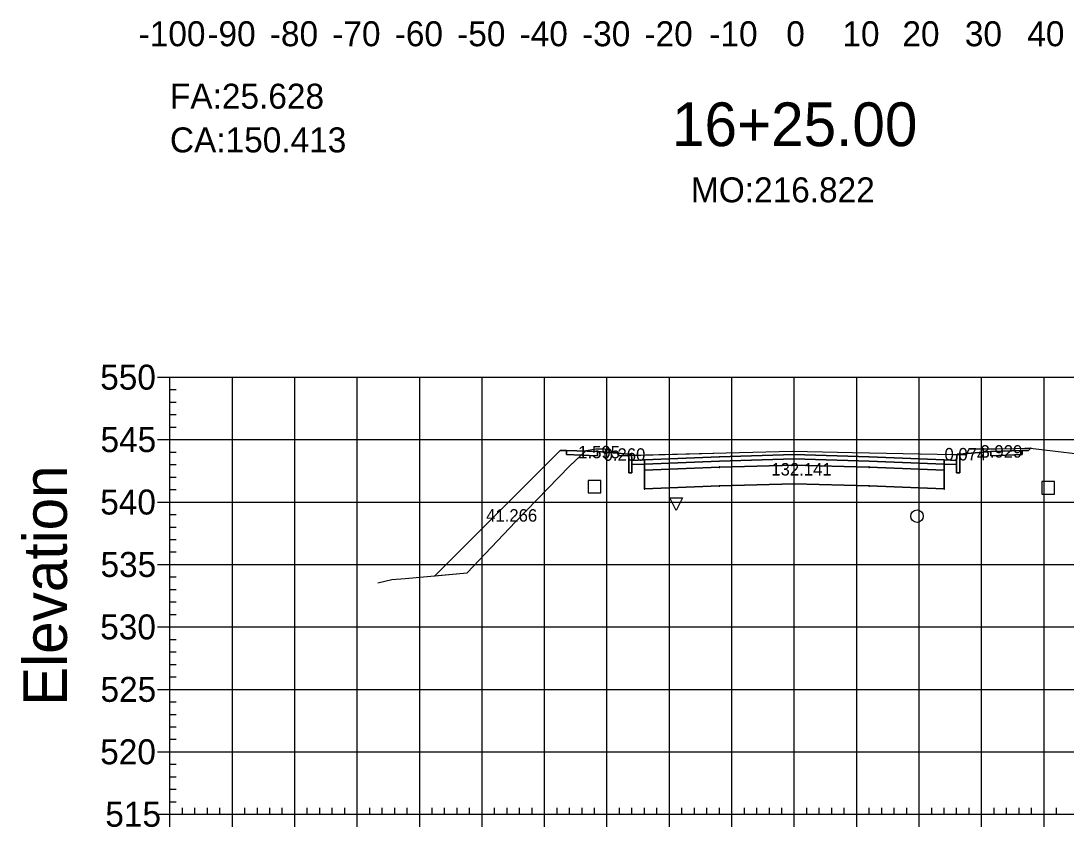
# Model space of a CAD drawing. Extents: x 704834 to 709892, y 372981 to 377533.
# Drawn here: x 704913 to 705080.4, y 373420.8 to 373549.9 of the extents above; entities that cross this region are included whole.
import ezdxf

# ---------------------------------------------------------------- set-up
doc = ezdxf.new("R2010")
doc.units = 0
for name, color, linetype in [('1', 7, 'Continuous'), ('10', 7, 'Continuous'), ('13', 7, 'Continuous'), ('14', 7, 'Continuous'), ('4', 7, 'Continuous'), ('57', 7, 'Continuous'), ('59', 7, 'Continuous'), ('60', 7, 'Continuous'), ('Default_Xsect', 7, 'Continuous'), ('Existing', 7, 'Continuous')]:
    doc.layers.add(name, color=color, linetype=linetype)

msp = doc.modelspace()

# ---------------------------------------------------------------- linework, layer by layer
for points in [[(704999.37, 373481.06), (704979.32, 373461)], [(705000.37, 373481.1), (704999.37, 373481.06)], [(705010.37, 373480.5), (705005.37, 373480.9)], [(705063.37, 373480.5), (705068.37, 373480.9)], [(705073.37, 373481.1), (705074.37, 373481.06)], [(705074.37, 373481.06), (705074.75, 373481.43)]]:
    msp.add_lwpolyline(points)
for points in [[(705005.37, 373480.9), (705000.37, 373481.1), (705000.37, 373480.43), (705005.37, 373480.23)], [(705068.37, 373480.23), (705073.37, 373480.43), (705073.37, 373481.1), (705068.37, 373480.9)], [(705010.87, 373479.5), (705010.79, 373480.5), (705010.37, 373480.5), (705010.37, 373477.5), (705010.87, 373477.5)], [(705012.87, 373479.58), (705010.87, 373479.5), (705010.87, 373478.83), (705012.87, 373478.91)], [(705036.87, 373479.75), (705048.87, 373479.39), (705060.87, 373478.91), (705060.87, 373479.58), (705048.87, 373480.06), (705036.87, 373480.42), (705024.87, 373480.06), (705012.87, 373479.58), (705012.87, 373478.91), (705024.87, 373479.39)], [(705036.87, 373478.75), (705048.87, 373478.39), (705060.87, 373477.91), (705060.87, 373478.91), (705048.87, 373479.39), (705036.87, 373479.75), (705024.87, 373479.39), (705012.87, 373478.91), (705012.87, 373477.91), (705024.87, 373478.39)], [(705036.82, 373479.7), (705036.92, 373479.7), (705036.92, 373479.8), (705036.82, 373479.8)], [(705060.87, 373478.91), (705062.87, 373478.83), (705062.87, 373479.5), (705060.87, 373479.58)], [(705062.87, 373477.5), (705063.37, 373477.5), (705063.37, 373480.5), (705062.96, 373480.5), (705062.87, 373479.5)], [(705012.82, 373477.86), (705012.92, 373477.86), (705012.92, 373477.96), (705012.82, 373477.96)], [(705036.87, 373475.75), (705048.87, 373475.39), (705060.87, 373474.91), (705060.87, 373477.91), (705048.87, 373478.39), (705036.87, 373478.75), (705024.87, 373478.39), (705012.87, 373477.91), (705012.87, 373474.91), (705024.87, 373475.39)], [(705024.82, 373478.34), (705024.92, 373478.34), (705024.92, 373478.44), (705024.82, 373478.44)], [(705036.82, 373478.7), (705036.92, 373478.7), (705036.92, 373478.8), (705036.82, 373478.8)], [(705048.82, 373478.34), (705048.92, 373478.34), (705048.92, 373478.44), (705048.82, 373478.44)], [(705060.82, 373477.86), (705060.92, 373477.86), (705060.92, 373477.96), (705060.82, 373477.96)], [(705012.82, 373474.86), (705012.92, 373474.86), (705012.92, 373474.96), (705012.82, 373474.96)], [(705024.82, 373475.34), (705024.92, 373475.34), (705024.92, 373475.44), (705024.82, 373475.44)], [(705036.82, 373475.7), (705036.92, 373475.7), (705036.92, 373475.8), (705036.82, 373475.8)], [(705048.82, 373475.34), (705048.92, 373475.34), (705048.92, 373475.44), (705048.82, 373475.44)], [(705060.82, 373474.86), (705060.92, 373474.86), (705060.92, 373474.96), (705060.82, 373474.96)]]:
    msp.add_lwpolyline(points, close=True)
at = {"layer": '1'}
for points in [[(704979.32, 373461), (704984.46, 373461.49), (704992.22, 373469.67), (705000.89, 373478.56), (705002.74, 373480.34), (705000.37, 373480.43), (705000.37, 373481.1), (704999.37, 373481.06)], [(705002.74, 373480.34), (705003.51, 373481.08), (705005.1, 373481.32), (705006.54, 373481.34), (705008.49, 373480.71), (705008.52, 373480.65), (705005.37, 373480.9), (705005.37, 373480.23)], [(705010.37, 373480.3), (705025.93, 373480.69), (705036.58, 373480.96), (705046.2, 373480.74), (705059.73, 373480.49), (705063.37, 373480.42), (705063.37, 373477.5), (705062.87, 373477.5), (705062.87, 373478.83), (705060.87, 373478.91), (705060.87, 373477.91), (705060.87, 373474.91), (705048.87, 373475.39), (705036.87, 373475.75), (705024.87, 373475.39), (705012.87, 373474.91), (705012.87, 373477.91), (705012.87, 373478.91), (705010.87, 373478.83), (705010.87, 373477.5), (705010.37, 373477.5)], [(705064.54, 373480.59), (705064.82, 373481.24), (705064.88, 373481.34), (705065.07, 373481.34), (705069.08, 373481.35), (705069.21, 373481.36), (705072.04, 373481.4), (705073.81, 373481.43), (705074.14, 373481.44), (705074.66, 373481.44), (705074.75, 373481.43), (705074.37, 373481.06), (705073.37, 373481.1), (705073.37, 373480.43), (705068.37, 373480.23), (705068.37, 373480.9)], [(705008.52, 373480.65), (705008.71, 373480.25), (705010.37, 373480.3), (705010.37, 373480.5)], [(705063.37, 373480.42), (705064.45, 373480.4), (705064.54, 373480.59), (705063.37, 373480.5)], [(705017.94, 373471.49), (705016.94, 373473.49), (705018.94, 373473.49)]]:
    msp.add_lwpolyline(points, close=True, dxfattribs=at)
at = {"layer": '10'}
msp.add_lwpolyline([(705003.88, 373474.28), (705005.88, 373474.28), (705005.88, 373476.28), (705003.88, 373476.28)], close=True, dxfattribs=at)
at = {"layer": '13'}
msp.add_circle((705056.52, 373470.55), 1, dxfattribs=at)
at = {"layer": '14'}
for points in [[(705074.75, 373481.43), (705074.75, 373481.48), (705074.75, 373481.43), (705074.7, 373481.43), (705074.75, 373481.43), (705074.75, 373481.38), (705074.75, 373481.43), (705074.8, 373481.43)], [(705012.87, 373479.58), (705012.87, 373479.63), (705012.87, 373479.58), (705012.82, 373479.58), (705012.87, 373479.58), (705012.87, 373479.53), (705012.87, 373479.58), (705012.92, 373479.58)], [(705024.87, 373480.06), (705024.87, 373480.11), (705024.87, 373480.06), (705024.82, 373480.06), (705024.87, 373480.06), (705024.87, 373480.01), (705024.87, 373480.06), (705024.92, 373480.06)], [(705036.87, 373480.42), (705036.87, 373480.47), (705036.87, 373480.42), (705036.82, 373480.42), (705036.87, 373480.42), (705036.87, 373480.37), (705036.87, 373480.42), (705036.92, 373480.42)], [(705048.87, 373480.06), (705048.87, 373480.11), (705048.87, 373480.06), (705048.82, 373480.06), (705048.87, 373480.06), (705048.87, 373480.01), (705048.87, 373480.06), (705048.92, 373480.06)], [(705060.87, 373479.58), (705060.87, 373479.63), (705060.87, 373479.58), (705060.82, 373479.58), (705060.87, 373479.58), (705060.87, 373479.53), (705060.87, 373479.58), (705060.92, 373479.58)], [(704979.32, 373461), (704979.32, 373461.05), (704979.32, 373461), (704979.27, 373461), (704979.32, 373461), (704979.32, 373460.95), (704979.32, 373461), (704979.37, 373461)]]:
    msp.add_lwpolyline(points, dxfattribs=at)
at = {"layer": '4'}
msp.add_lwpolyline([(705076.52, 373474.1), (705078.52, 373474.1), (705078.52, 373476.1), (705076.52, 373476.1)], close=True, dxfattribs=at)
at = {"layer": '57'}
for p, q in [((704934.87, 373492.82), (704936.87, 373492.82)), ((704936.87, 373492.82), (705136.87, 373492.82)), ((704936.87, 373422.82), (704936.87, 373492.82)), ((704936.87, 373422.82), (704936.87, 373492.82)), ((704946.87, 373422.82), (704946.87, 373492.82)), ((704956.87, 373422.82), (704956.87, 373492.82)), ((704966.87, 373422.82), (704966.87, 373492.82)), ((704976.87, 373422.82), (704976.87, 373492.82)), ((704986.87, 373422.82), (704986.87, 373492.82)), ((704996.87, 373422.82), (704996.87, 373492.82)), ((705006.87, 373422.82), (705006.87, 373492.82)), ((705016.87, 373422.82), (705016.87, 373492.82)), ((705026.87, 373422.82), (705026.87, 373492.82)), ((705036.87, 373422.82), (705036.87, 373492.82)), ((705046.87, 373422.82), (705046.87, 373492.82)), ((705056.87, 373422.82), (705056.87, 373492.82)), ((705066.87, 373422.82), (705066.87, 373492.82)), ((705076.87, 373422.82), (705076.87, 373492.82)), ((704936.87, 373490.82), (704937.87, 373490.82)), ((704936.87, 373488.82), (704937.87, 373488.82)), ((704936.87, 373486.82), (704937.87, 373486.82)), ((704936.87, 373484.82), (704937.87, 373484.82)), ((704934.87, 373482.82), (704936.87, 373482.82)), ((704936.87, 373482.82), (705136.87, 373482.82)), ((704936.87, 373480.82), (704937.87, 373480.82)), ((704936.87, 373478.82), (704937.87, 373478.82)), ((704936.87, 373476.82), (704937.87, 373476.82)), ((704936.87, 373474.82), (704937.87, 373474.82)), ((704934.87, 373472.82), (704936.87, 373472.82)), ((704936.87, 373472.82), (705136.87, 373472.82)), ((704936.87, 373470.82), (704937.87, 373470.82)), ((704936.87, 373468.82), (704937.87, 373468.82)), ((704936.87, 373466.82), (704937.87, 373466.82)), ((704936.87, 373464.82), (704937.87, 373464.82)), ((704934.87, 373462.82), (704936.87, 373462.82)), ((704936.87, 373462.82), (705136.87, 373462.82)), ((704936.87, 373460.82), (704937.87, 373460.82)), ((704936.87, 373458.82), (704937.87, 373458.82)), ((704936.87, 373456.82), (704937.87, 373456.82)), ((704936.87, 373454.82), (704937.87, 373454.82)), ((704934.87, 373452.82), (704936.87, 373452.82)), ((704936.87, 373452.82), (705136.87, 373452.82)), ((704936.87, 373450.82), (704937.87, 373450.82)), ((704936.87, 373448.82), (704937.87, 373448.82)), ((704936.87, 373446.82), (704937.87, 373446.82)), ((704936.87, 373444.82), (704937.87, 373444.82)), ((704934.87, 373442.82), (704936.87, 373442.82)), ((704936.87, 373442.82), (705136.87, 373442.82)), ((704936.87, 373440.82), (704937.87, 373440.82)), ((704936.87, 373438.82), (704937.87, 373438.82)), ((704936.87, 373436.82), (704937.87, 373436.82)), ((704936.87, 373434.82), (704937.87, 373434.82)), ((704934.87, 373432.82), (704936.87, 373432.82)), ((704936.87, 373432.82), (705136.87, 373432.82)), ((704936.87, 373430.82), (704937.87, 373430.82)), ((704936.87, 373428.82), (704937.87, 373428.82)), ((704936.87, 373426.82), (704937.87, 373426.82)), ((704936.87, 373424.82), (704937.87, 373424.82)), ((704934.87, 373422.82), (704936.87, 373422.82)), ((704936.87, 373422.82), (705136.87, 373422.82)), ((704936.87, 373422.82), (705136.87, 373422.82)), ((704936.87, 373420.82), (704936.87, 373422.82)), ((704938.87, 373422.82), (704938.87, 373423.82)), ((704940.87, 373422.82), (704940.87, 373423.82)), ((704942.87, 373422.82), (704942.87, 373423.82)), ((704944.87, 373422.82), (704944.87, 373423.82)), ((704946.87, 373420.82), (704946.87, 373422.82)), ((704948.87, 373422.82), (704948.87, 373423.82)), ((704950.87, 373422.82), (704950.87, 373423.82)), ((704952.87, 373422.82), (704952.87, 373423.82)), ((704954.87, 373422.82), (704954.87, 373423.82)), ((704956.87, 373420.82), (704956.87, 373422.82)), ((704958.87, 373422.82), (704958.87, 373423.82)), ((704960.87, 373422.82), (704960.87, 373423.82)), ((704962.87, 373422.82), (704962.87, 373423.82)), ((704964.87, 373422.82), (704964.87, 373423.82)), ((704966.87, 373420.82), (704966.87, 373422.82)), ((704968.87, 373422.82), (704968.87, 373423.82)), ((704970.87, 373422.82), (704970.87, 373423.82)), ((704972.87, 373422.82), (704972.87, 373423.82)), ((704974.87, 373422.82), (704974.87, 373423.82)), ((704976.87, 373420.82), (704976.87, 373422.82)), ((704978.87, 373422.82), (704978.87, 373423.82)), ((704980.87, 373422.82), (704980.87, 373423.82)), ((704982.87, 373422.82), (704982.87, 373423.82)), ((704984.87, 373422.82), (704984.87, 373423.82)), ((704986.87, 373420.82), (704986.87, 373422.82)), ((704988.87, 373422.82), (704988.87, 373423.82)), ((704990.87, 373422.82), (704990.87, 373423.82)), ((704992.87, 373422.82), (704992.87, 373423.82)), ((704994.87, 373422.82), (704994.87, 373423.82)), ((704996.87, 373420.82), (704996.87, 373422.82)), ((704998.87, 373422.82), (704998.87, 373423.82)), ((705000.87, 373422.82), (705000.87, 373423.82)), ((705002.87, 373422.82), (705002.87, 373423.82)), ((705004.87, 373422.82), (705004.87, 373423.82)), ((705006.87, 373420.82), (705006.87, 373422.82)), ((705008.87, 373422.82), (705008.87, 373423.82)), ((705010.87, 373422.82), (705010.87, 373423.82)), ((705012.87, 373422.82), (705012.87, 373423.82)), ((705014.87, 373422.82), (705014.87, 373423.82)), ((705016.87, 373420.82), (705016.87, 373422.82)), ((705018.87, 373422.82), (705018.87, 373423.82)), ((705020.87, 373422.82), (705020.87, 373423.82)), ((705022.87, 373422.82), (705022.87, 373423.82)), ((705024.87, 373422.82), (705024.87, 373423.82)), ((705026.87, 373420.82), (705026.87, 373422.82)), ((705028.87, 373422.82), (705028.87, 373423.82)), ((705030.87, 373422.82), (705030.87, 373423.82)), ((705032.87, 373422.82), (705032.87, 373423.82)), ((705034.87, 373422.82), (705034.87, 373423.82)), ((705036.87, 373420.82), (705036.87, 373422.82)), ((705038.87, 373422.82), (705038.87, 373423.82)), ((705040.87, 373422.82), (705040.87, 373423.82)), ((705042.87, 373422.82), (705042.87, 373423.82)), ((705044.87, 373422.82), (705044.87, 373423.82)), ((705046.87, 373420.82), (705046.87, 373422.82)), ((705048.87, 373422.82), (705048.87, 373423.82)), ((705050.87, 373422.82), (705050.87, 373423.82)), ((705052.87, 373422.82), (705052.87, 373423.82)), ((705054.87, 373422.82), (705054.87, 373423.82)), ((705056.87, 373420.82), (705056.87, 373422.82)), ((705058.87, 373422.82), (705058.87, 373423.82)), ((705060.87, 373422.82), (705060.87, 373423.82)), ((705062.87, 373422.82), (705062.87, 373423.82)), ((705064.87, 373422.82), (705064.87, 373423.82)), ((705066.87, 373420.82), (705066.87, 373422.82)), ((705068.87, 373422.82), (705068.87, 373423.82)), ((705070.87, 373422.82), (705070.87, 373423.82)), ((705072.87, 373422.82), (705072.87, 373423.82)), ((705074.87, 373422.82), (705074.87, 373423.82)), ((705076.87, 373420.82), (705076.87, 373422.82)), ((705078.87, 373422.82), (705078.87, 373423.82))]:
    msp.add_line(p, q, dxfattribs=at)
at = {"layer": 'Default_Xsect'}
msp.add_lwpolyline([(704979.32, 373461), (704999.37, 373481.06), (705000.37, 373481.1), (705005.37, 373480.9), (705010.37, 373480.5), (705010.79, 373480.5), (705010.87, 373479.5), (705012.87, 373479.58), (705024.87, 373480.06), (705036.87, 373480.42), (705048.87, 373480.06), (705060.87, 373479.58), (705062.87, 373479.5), (705062.96, 373480.5), (705063.37, 373480.5), (705068.37, 373480.9), (705073.37, 373481.1), (705074.37, 373481.06), (705074.75, 373481.43)], dxfattribs=at)
at = {"layer": 'Existing'}
msp.add_lwpolyline([(704970.16, 373459.89), (704972.39, 373460.4), (704974.56, 373460.55), (704984.46, 373461.49), (704992.22, 373469.67), (705000.89, 373478.56), (705003.51, 373481.08), (705005.1, 373481.32), (705006.54, 373481.34), (705008.49, 373480.71), (705008.71, 373480.25), (705025.93, 373480.69), (705036.58, 373480.96), (705046.2, 373480.74), (705059.73, 373480.49), (705064.45, 373480.4), (705064.82, 373481.24), (705064.88, 373481.34), (705065.07, 373481.34), (705069.08, 373481.35), (705069.21, 373481.36), (705072.04, 373481.4), (705073.81, 373481.43), (705074.14, 373481.44), (705074.66, 373481.44), (705075.1, 373481.38), (705082.27, 373480.56)], dxfattribs=at)

# ---------------------------------------------------------------- texts
msp.add_text('CA:150.413', height=4).set_placement((704936.87, 373528.82))
at = {"layer": '1'}
msp.add_text('16+25.00', height=7, dxfattribs=at).set_placement((705017.28, 373529.82))
at = {"layer": '14'}
for p in [(705000.34, 373481.05), (705073.34, 373481.05), (705000.34, 373480.38), (705005.34, 373480.18), (705068.34, 373480.18), (705073.34, 373480.38)]:
    msp.add_text('+', height=0.1, dxfattribs=at).set_placement(p)
at = {"layer": '57'}
for s, p in [('-100', (704931.86, 373545.82)), ('-90', (704942.87, 373545.82)), ('-80', (704952.87, 373545.82)), ('-70', (704962.87, 373545.82)), ('-60', (704972.87, 373545.82)), ('-50', (704982.87, 373545.82)), ('-40', (704992.87, 373545.82)), ('-30', (705002.87, 373545.82)), ('-20', (705012.87, 373545.82)), ('-10', (705023.26, 373545.82)), ('0', (705035.58, 373545.82)), ('10', (705044.57, 373545.82)), ('20', (705054.18, 373545.82)), ('30', (705064.18, 373545.82)), ('40', (705074.18, 373545.82)), ('550', (704925.7, 373490.82)), ('545', (704925.75, 373480.82)), ('540', (704925.7, 373470.82)), ('535', (704925.75, 373460.82)), ('530', (704925.7, 373450.82)), ('525', (704925.75, 373440.82)), ('520', (704925.7, 373430.82)), ('515', (704926.52, 373420.82))]:
    msp.add_text(s, height=4, dxfattribs=at).set_placement(p)
at = {"layer": '59'}
for s, height, p in [('FA:25.628', 4, (704936.87, 373535.82)), ('MO:216.822', 4, (705020.32, 373520.82)), ('1.595', 2, (705002.26, 373479.82)), ('0.260', 2, (705006.32, 373479.43)), ('0.074', 2, (705060.92, 373479.48)), ('3.929', 2, (705066.69, 373479.93)), ('132.141', 2, (705033.18, 373477.07)), ('41.266', 2, (704987.51, 373469.68))]:
    msp.add_text(s, height=height, dxfattribs=at).set_placement(p)
at = {"layer": '60'}
msp.add_text('Elevation', height=7, rotation=90, dxfattribs=at).set_placement((704920.37, 373440.18))

doc.saveas('drawing.dxf')
